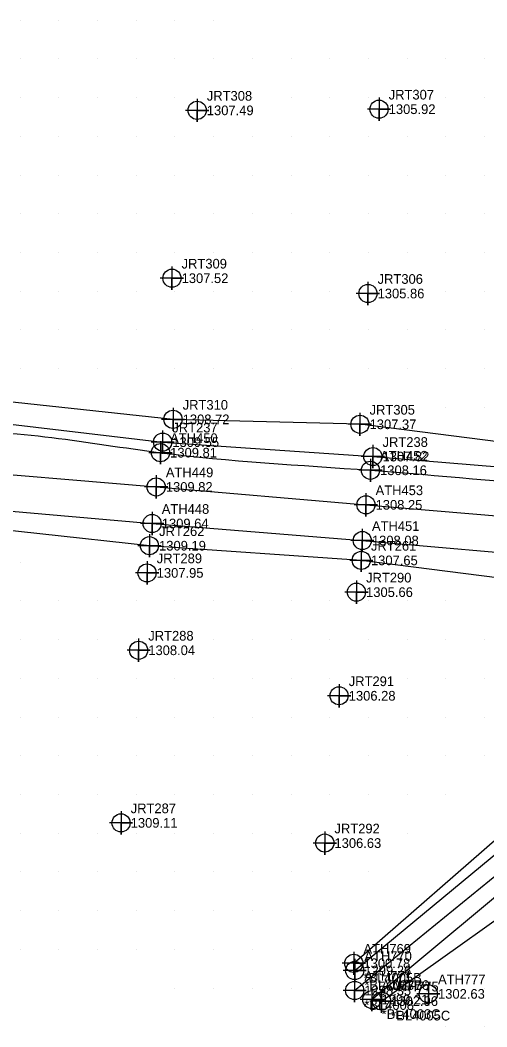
# Model space of a CAD drawing. Extents: x 1234484 to 1235382, y 695050 to 695510.
# Drawn here: x 1234680 to 1234800.6, y 695200 to 695460 of the extents above; entities that cross this region are included whole.
import ezdxf

# ---------------------------------------------------------------- set-up
doc = ezdxf.new("R2010")
doc.units = 0
for name, color, linetype in [('Exist DTM Breakline', 7, 'Continuous'), ('Exist DTM Breakline Cogo Comment', 7, 'Continuous'), ('Exist DTM Breakline Cogo Elevation', 7, 'Continuous'), ('Exist DTM Breakline Cogo Number', 7, 'Continuous'), ('Exist DTM Breakline Cogo Point CELL', 7, 'Continuous'), ('Exist DTM Breakline Underwater', 7, 'Continuous'), ('Exist DTM Crownline', 7, 'Continuous'), ('Exist DTM Crownline Cogo Elevation', 7, 'Continuous'), ('Exist DTM Crownline Cogo Number', 7, 'Continuous'), ('Exist DTM Crownline Cogo Point CELL', 7, 'Continuous'), ('Exist DTM Drainline Cogo Comment', 7, 'Continuous'), ('Exist DTM Drainline Cogo Elevation', 7, 'Continuous'), ('Exist DTM Drainline Cogo Number', 7, 'Continuous'), ('Exist DTM Drainline Cogo Point CELL', 7, 'Continuous'), ('Exist DTM QL2 LIDAR Elevation Point', 7, 'Continuous'), ('Exist DTM Regular Point CELL', 7, 'Continuous'), ('Exist DTM Regular Point Cogo Elevation', 7, 'Continuous'), ('Exist DTM Regular Point Cogo Number', 7, 'Continuous'), ('Exist DTM Regular Point Underwater CELL', 7, 'Continuous'), ('Exist DTM Regular Point Underwater Cogo Comment', 7, 'Continuous'), ('Exist DTM Regular Point Underwater Cogo Elevation', 7, 'Continuous'), ('Exist DTM Regular Point Underwater Cogo Number', 7, 'Continuous'), ('Exist Hydro Stream or Body of Water', 7, 'Continuous'), ('Exist Roads EOP', 7, 'Continuous'), ('Exist Roads EOP Cogo Elevation', 7, 'Continuous'), ('Exist Roads EOP Cogo Number', 7, 'Continuous'), ('Exist Roads EOP Cogo Point CELL', 7, 'Continuous')]:
    doc.layers.add(name, color=color, linetype=linetype)

msp = doc.modelspace()

# ---------------------------------------------------------------- linework, layer by layer
at = {"layer": 'Exist DTM Breakline'}
for points in [[(1234866.911, 695345.376), (1234823.763, 695348.478), (1234767.785, 695355.619), (1234719.498, 695356.897), (1234661.167, 695363.182), (1234623.376, 695365.3), (1234610.221, 695366.341), (1234608.231, 695369.759), (1234607.001, 695375.947)], [(1234608.156, 695366.132), (1234620.219, 695363.657), (1234657.83, 695357.954), (1234716.822, 695351.015), (1234771.134, 695347.284), (1234823.515, 695343.018), (1234867.598, 695341.251), (1234907.686, 695335.753), (1234932.171, 695332.602)], [(1234900.418, 695309.093), (1234843.128, 695314.065), (1234821.486, 695313.61), (1234768.142, 695320.476), (1234713.4, 695324.265), (1234656.708, 695330.451), (1234602.942, 695334.287)], [(1234766.2, 695216.412), (1234807.252, 695252.276), (1234839.673, 695274.467), (1234869.326, 695284.86), (1234890.801, 695299.09), (1234911.196, 695302.79), (1234918.594, 695307.818)], [(1234773.364, 695206.653), (1234820.257, 695240.015), (1234835.082, 695253.487), (1234852.804, 695270.766)]]:
    msp.add_lwpolyline(points, dxfattribs=at)
at = {"layer": 'Exist DTM Breakline Cogo Point CELL'}
for points in [[(1234719.498, 695359.897), (1234719.498, 695353.897), (1234719.498, 695356.897), (1234722.498, 695356.897), (1234716.498, 695356.897)], [(1234767.785, 695358.619), (1234767.785, 695352.619), (1234767.785, 695355.619), (1234770.785, 695355.619), (1234764.785, 695355.619)], [(1234716.822, 695354.015), (1234716.822, 695348.015), (1234716.822, 695351.015), (1234719.822, 695351.015), (1234713.822, 695351.015)], [(1234771.134, 695350.284), (1234771.134, 695344.284), (1234771.134, 695347.284), (1234774.134, 695347.284), (1234768.134, 695347.284)], [(1234713.4, 695327.265), (1234713.4, 695321.265), (1234713.4, 695324.265), (1234716.4, 695324.265), (1234710.4, 695324.265)], [(1234768.142, 695323.476), (1234768.142, 695317.476), (1234768.142, 695320.476), (1234771.142, 695320.476), (1234765.142, 695320.476)], [(1234766.2, 695219.412), (1234766.2, 695213.412), (1234766.2, 695216.412), (1234769.2, 695216.412), (1234763.2, 695216.412)], [(1234773.364, 695209.653), (1234773.364, 695203.653), (1234773.364, 695206.653), (1234776.364, 695206.653), (1234770.364, 695206.653)]]:
    msp.add_lwpolyline(points, dxfattribs=at)
for centre in [(1234719.498, 695356.897), (1234767.785, 695355.619), (1234716.822, 695351.015), (1234771.134, 695347.284), (1234713.4, 695324.265), (1234768.142, 695320.476), (1234766.2, 695216.412), (1234773.364, 695206.653)]:
    msp.add_circle(centre, 2.344, dxfattribs=at)
at = {"layer": 'Exist DTM Breakline Underwater'}
msp.add_lwpolyline([(1234766.421, 695209.389), (1234812.885, 695247.237), (1234843.411, 695272.621), (1234869.986, 695279.055), (1234895.378, 695289.036), (1234916.238, 695295.408), (1234934.131, 695306.081), (1234961.466, 695329.617), (1234991.436, 695342.664), (1235009.265, 695346.147), (1235040.352, 695365.623), (1235072.367, 695380.008), (1235092.174, 695396.335)], dxfattribs=at)
at = {"layer": 'Exist DTM Crownline'}
msp.add_lwpolyline([(1234511.603, 695359.057), (1234605.73, 695349.422), (1234657.657, 695344.297), (1234715.146, 695339.445), (1234769.335, 695334.825), (1234822.546, 695330.321), (1234845.176, 695328.304), (1234903.738, 695322.57)], dxfattribs=at)
at = {"layer": 'Exist DTM Crownline Cogo Point CELL'}
for points in [[(1234715.146, 695342.445), (1234715.146, 695336.445), (1234715.146, 695339.445), (1234718.146, 695339.445), (1234712.146, 695339.445)], [(1234769.335, 695337.825), (1234769.335, 695331.825), (1234769.335, 695334.825), (1234772.335, 695334.825), (1234766.335, 695334.825)]]:
    msp.add_lwpolyline(points, dxfattribs=at)
for centre in [(1234715.146, 695339.445), (1234769.335, 695334.825)]:
    msp.add_circle(centre, 2.344, dxfattribs=at)
at = {"layer": 'Exist DTM Drainline Cogo Point CELL'}
for points in [[(1234766.439, 695217.543), (1234766.439, 695211.543), (1234766.439, 695214.543), (1234769.439, 695214.543), (1234763.439, 695214.543)], [(1234770.872, 695210.044), (1234770.872, 695204.044), (1234770.872, 695207.044), (1234773.872, 695207.044), (1234767.872, 695207.044)]]:
    msp.add_lwpolyline(points, dxfattribs=at)
for centre in [(1234766.439, 695214.543), (1234770.872, 695207.044)]:
    msp.add_circle(centre, 2.344, dxfattribs=at)
at = {"layer": 'Exist DTM QL2 LIDAR Elevation Point'}
for p, q in [((1234680, 695460), (1234680, 695460)), ((1234690, 695460), (1234690, 695460)), ((1234700, 695460), (1234700, 695460)), ((1234710, 695460), (1234710, 695460)), ((1234720, 695460), (1234720, 695460)), ((1234730, 695460), (1234730, 695460)), ((1234680, 695450), (1234680, 695450)), ((1234690, 695450), (1234690, 695450)), ((1234700, 695450), (1234700, 695450)), ((1234710, 695450), (1234710, 695450)), ((1234720, 695450), (1234720, 695450)), ((1234730, 695450), (1234730, 695450)), ((1234740, 695450), (1234740, 695450)), ((1234750, 695450), (1234750, 695450)), ((1234760, 695450), (1234760, 695450)), ((1234770, 695450), (1234770, 695450)), ((1234780, 695450), (1234780, 695450)), ((1234790, 695450), (1234790, 695450)), ((1234800, 695450), (1234800, 695450)), ((1234680, 695440), (1234680, 695440)), ((1234690, 695440), (1234690, 695440)), ((1234700, 695440), (1234700, 695440)), ((1234710, 695440), (1234710, 695440)), ((1234720, 695440), (1234720, 695440)), ((1234730, 695440), (1234730, 695440)), ((1234740, 695440), (1234740, 695440)), ((1234750, 695440), (1234750, 695440)), ((1234760, 695440), (1234760, 695440)), ((1234770, 695440), (1234770, 695440)), ((1234780, 695440), (1234780, 695440)), ((1234790, 695440), (1234790, 695440)), ((1234800, 695440), (1234800, 695440)), ((1234680, 695430), (1234680, 695430)), ((1234690, 695430), (1234690, 695430)), ((1234700, 695430), (1234700, 695430)), ((1234710, 695430), (1234710, 695430)), ((1234720, 695430), (1234720, 695430)), ((1234730, 695430), (1234730, 695430)), ((1234740, 695430), (1234740, 695430)), ((1234750, 695430), (1234750, 695430)), ((1234760, 695430), (1234760, 695430)), ((1234770, 695430), (1234770, 695430)), ((1234780, 695430), (1234780, 695430)), ((1234790, 695430), (1234790, 695430)), ((1234800, 695430), (1234800, 695430)), ((1234680, 695420), (1234680, 695420)), ((1234690, 695420), (1234690, 695420)), ((1234700, 695420), (1234700, 695420)), ((1234710, 695420), (1234710, 695420)), ((1234720, 695420), (1234720, 695420)), ((1234730, 695420), (1234730, 695420)), ((1234740, 695420), (1234740, 695420)), ((1234750, 695420), (1234750, 695420)), ((1234760, 695420), (1234760, 695420)), ((1234770, 695420), (1234770, 695420)), ((1234780, 695420), (1234780, 695420)), ((1234790, 695420), (1234790, 695420)), ((1234800, 695420), (1234800, 695420)), ((1234680, 695410), (1234680, 695410)), ((1234690, 695410), (1234690, 695410)), ((1234700, 695410), (1234700, 695410)), ((1234710, 695410), (1234710, 695410)), ((1234720, 695410), (1234720, 695410)), ((1234730, 695410), (1234730, 695410)), ((1234740, 695410), (1234740, 695410)), ((1234750, 695410), (1234750, 695410)), ((1234760, 695410), (1234760, 695410)), ((1234770, 695410), (1234770, 695410)), ((1234780, 695410), (1234780, 695410)), ((1234790, 695410), (1234790, 695410)), ((1234800, 695410), (1234800, 695410)), ((1234680, 695400), (1234680, 695400)), ((1234690, 695400), (1234690, 695400)), ((1234700, 695400), (1234700, 695400)), ((1234710, 695400), (1234710, 695400)), ((1234720, 695400), (1234720, 695400)), ((1234730, 695400), (1234730, 695400)), ((1234740, 695400), (1234740, 695400)), ((1234750, 695400), (1234750, 695400)), ((1234760, 695400), (1234760, 695400)), ((1234770, 695400), (1234770, 695400)), ((1234780, 695400), (1234780, 695400)), ((1234790, 695400), (1234790, 695400)), ((1234800, 695400), (1234800, 695400)), ((1234680, 695390), (1234680, 695390)), ((1234690, 695390), (1234690, 695390)), ((1234700, 695390), (1234700, 695390)), ((1234710, 695390), (1234710, 695390)), ((1234720, 695390), (1234720, 695390)), ((1234730, 695390), (1234730, 695390)), ((1234740, 695390), (1234740, 695390)), ((1234750, 695390), (1234750, 695390)), ((1234760, 695390), (1234760, 695390)), ((1234770, 695390), (1234770, 695390)), ((1234780, 695390), (1234780, 695390)), ((1234790, 695390), (1234790, 695390)), ((1234800, 695390), (1234800, 695390)), ((1234680, 695380), (1234680, 695380)), ((1234690, 695380), (1234690, 695380)), ((1234700, 695380), (1234700, 695380)), ((1234710, 695380), (1234710, 695380)), ((1234720, 695380), (1234720, 695380)), ((1234730, 695380), (1234730, 695380)), ((1234740, 695380), (1234740, 695380)), ((1234750, 695380), (1234750, 695380)), ((1234760, 695380), (1234760, 695380)), ((1234770, 695380), (1234770, 695380)), ((1234780, 695380), (1234780, 695380)), ((1234790, 695380), (1234790, 695380)), ((1234800, 695380), (1234800, 695380)), ((1234680, 695370), (1234680, 695370)), ((1234690, 695370), (1234690, 695370)), ((1234700, 695370), (1234700, 695370)), ((1234710, 695370), (1234710, 695370)), ((1234720, 695370), (1234720, 695370)), ((1234730, 695370), (1234730, 695370)), ((1234740, 695370), (1234740, 695370)), ((1234750, 695370), (1234750, 695370)), ((1234760, 695370), (1234760, 695370)), ((1234770, 695370), (1234770, 695370)), ((1234780, 695370), (1234780, 695370)), ((1234790, 695370), (1234790, 695370)), ((1234800, 695370), (1234800, 695370)), ((1234780, 695360), (1234780, 695360)), ((1234790, 695360), (1234790, 695360)), ((1234800, 695360), (1234800, 695360)), ((1234680, 695320), (1234680, 695320)), ((1234680, 695310), (1234680, 695310)), ((1234690, 695310), (1234690, 695310)), ((1234700, 695310), (1234700, 695310)), ((1234710, 695310), (1234710, 695310)), ((1234720, 695310), (1234720, 695310)), ((1234730, 695310), (1234730, 695310)), ((1234740, 695310), (1234740, 695310)), ((1234750, 695310), (1234750, 695310)), ((1234760, 695310), (1234760, 695310)), ((1234770, 695310), (1234770, 695310)), ((1234780, 695310), (1234780, 695310)), ((1234790, 695310), (1234790, 695310)), ((1234680, 695300), (1234680, 695300)), ((1234690, 695300), (1234690, 695300)), ((1234700, 695300), (1234700, 695300)), ((1234710, 695300), (1234710, 695300)), ((1234720, 695300), (1234720, 695300)), ((1234730, 695300), (1234730, 695300)), ((1234740, 695300), (1234740, 695300)), ((1234750, 695300), (1234750, 695300)), ((1234760, 695300), (1234760, 695300)), ((1234770, 695300), (1234770, 695300)), ((1234780, 695300), (1234780, 695300)), ((1234790, 695300), (1234790, 695300)), ((1234800, 695300), (1234800, 695300)), ((1234680, 695290), (1234680, 695290)), ((1234690, 695290), (1234690, 695290)), ((1234700, 695290), (1234700, 695290)), ((1234710, 695290), (1234710, 695290)), ((1234720, 695290), (1234720, 695290)), ((1234730, 695290), (1234730, 695290)), ((1234740, 695290), (1234740, 695290)), ((1234750, 695290), (1234750, 695290)), ((1234760, 695290), (1234760, 695290)), ((1234770, 695290), (1234770, 695290)), ((1234780, 695290), (1234780, 695290)), ((1234790, 695290), (1234790, 695290)), ((1234800, 695290), (1234800, 695290)), ((1234680, 695280), (1234680, 695280)), ((1234690, 695280), (1234690, 695280)), ((1234700, 695280), (1234700, 695280)), ((1234710, 695280), (1234710, 695280)), ((1234720, 695280), (1234720, 695280)), ((1234730, 695280), (1234730, 695280)), ((1234740, 695280), (1234740, 695280)), ((1234750, 695280), (1234750, 695280)), ((1234760, 695280), (1234760, 695280)), ((1234770, 695280), (1234770, 695280)), ((1234780, 695280), (1234780, 695280)), ((1234790, 695280), (1234790, 695280)), ((1234800, 695280), (1234800, 695280)), ((1234680, 695270), (1234680, 695270)), ((1234690, 695270), (1234690, 695270)), ((1234700, 695270), (1234700, 695270)), ((1234710, 695270), (1234710, 695270)), ((1234720, 695270), (1234720, 695270)), ((1234730, 695270), (1234730, 695270)), ((1234740, 695270), (1234740, 695270)), ((1234750, 695270), (1234750, 695270)), ((1234760, 695270), (1234760, 695270)), ((1234770, 695270), (1234770, 695270)), ((1234780, 695270), (1234780, 695270)), ((1234790, 695270), (1234790, 695270)), ((1234800, 695270), (1234800, 695270)), ((1234680, 695260), (1234680, 695260)), ((1234690, 695260), (1234690, 695260)), ((1234700, 695260), (1234700, 695260)), ((1234710, 695260), (1234710, 695260)), ((1234720, 695260), (1234720, 695260)), ((1234730, 695260), (1234730, 695260)), ((1234740, 695260), (1234740, 695260)), ((1234750, 695260), (1234750, 695260)), ((1234760, 695260), (1234760, 695260)), ((1234770, 695260), (1234770, 695260)), ((1234780, 695260), (1234780, 695260)), ((1234790, 695260), (1234790, 695260)), ((1234680, 695250), (1234680, 695250)), ((1234690, 695250), (1234690, 695250)), ((1234700, 695250), (1234700, 695250)), ((1234710, 695250), (1234710, 695250)), ((1234720, 695250), (1234720, 695250)), ((1234730, 695250), (1234730, 695250)), ((1234740, 695250), (1234740, 695250)), ((1234750, 695250), (1234750, 695250)), ((1234760, 695250), (1234760, 695250)), ((1234770, 695250), (1234770, 695250)), ((1234780, 695250), (1234780, 695250)), ((1234680, 695240), (1234680, 695240)), ((1234690, 695240), (1234690, 695240)), ((1234700, 695240), (1234700, 695240)), ((1234710, 695240), (1234710, 695240)), ((1234720, 695240), (1234720, 695240)), ((1234730, 695240), (1234730, 695240)), ((1234740, 695240), (1234740, 695240)), ((1234750, 695240), (1234750, 695240)), ((1234760, 695240), (1234760, 695240)), ((1234770, 695240), (1234770, 695240)), ((1234680, 695230), (1234680, 695230)), ((1234690, 695230), (1234690, 695230)), ((1234700, 695230), (1234700, 695230)), ((1234710, 695230), (1234710, 695230)), ((1234720, 695230), (1234720, 695230)), ((1234730, 695230), (1234730, 695230)), ((1234740, 695230), (1234740, 695230)), ((1234750, 695230), (1234750, 695230)), ((1234760, 695230), (1234760, 695230)), ((1234680, 695220), (1234680, 695220)), ((1234690, 695220), (1234690, 695220)), ((1234700, 695220), (1234700, 695220)), ((1234710, 695220), (1234710, 695220)), ((1234720, 695220), (1234720, 695220)), ((1234730, 695220), (1234730, 695220)), ((1234740, 695220), (1234740, 695220)), ((1234750, 695220), (1234750, 695220)), ((1234720, 695210), (1234720, 695210)), ((1234730, 695210), (1234730, 695210)), ((1234740, 695210), (1234740, 695210)), ((1234750, 695210), (1234750, 695210)), ((1234760, 695210), (1234760, 695210)), ((1234800, 695210), (1234800, 695210)), ((1234790, 695200), (1234790, 695200)), ((1234800, 695200), (1234800, 695200))]:
    msp.add_line(p, q, dxfattribs=at)
at = {"layer": 'Exist DTM Regular Point CELL'}
for points in [[(1234725.732, 695439.701), (1234725.732, 695433.701), (1234725.732, 695436.701), (1234728.732, 695436.701), (1234722.732, 695436.701)], [(1234772.723, 695439.998), (1234772.723, 695433.998), (1234772.723, 695436.998), (1234775.723, 695436.998), (1234769.723, 695436.998)], [(1234719.217, 695396.346), (1234719.217, 695390.346), (1234719.217, 695393.346), (1234722.217, 695393.346), (1234716.217, 695393.346)], [(1234769.856, 695392.397), (1234769.856, 695386.397), (1234769.856, 695389.397), (1234772.856, 695389.397), (1234766.856, 695389.397)], [(1234712.79, 695320.242), (1234712.79, 695314.242), (1234712.79, 695317.242), (1234715.79, 695317.242), (1234709.79, 695317.242)], [(1234766.879, 695315.27), (1234766.879, 695309.27), (1234766.879, 695312.27), (1234769.879, 695312.27), (1234763.879, 695312.27)], [(1234710.611, 695300.261), (1234710.611, 695294.261), (1234710.611, 695297.261), (1234713.611, 695297.261), (1234707.611, 695297.261)], [(1234762.4, 695288.509), (1234762.4, 695282.509), (1234762.4, 695285.509), (1234765.4, 695285.509), (1234759.4, 695285.509)], [(1234706.067, 695255.685), (1234706.067, 695249.685), (1234706.067, 695252.685), (1234709.067, 695252.685), (1234703.067, 695252.685)], [(1234758.711, 695250.468), (1234758.711, 695244.468), (1234758.711, 695247.468), (1234761.711, 695247.468), (1234755.711, 695247.468)], [(1234785.464, 695211.52), (1234785.464, 695205.52), (1234785.464, 695208.52), (1234788.464, 695208.52), (1234782.464, 695208.52)]]:
    msp.add_lwpolyline(points, dxfattribs=at)
for centre in [(1234725.732, 695436.701), (1234772.723, 695436.998), (1234719.217, 695393.346), (1234769.856, 695389.397), (1234712.79, 695317.242), (1234766.879, 695312.27), (1234710.611, 695297.261), (1234762.4, 695285.509), (1234706.067, 695252.685), (1234758.711, 695247.468), (1234785.464, 695208.52)]:
    msp.add_circle(centre, 2.344, dxfattribs=at)
at = {"layer": 'Exist DTM Regular Point Underwater CELL'}
msp.add_lwpolyline([(1234766.421, 695212.389), (1234766.421, 695206.389), (1234766.421, 695209.389), (1234769.421, 695209.389), (1234763.421, 695209.389)], dxfattribs=at)
msp.add_circle((1234766.421, 695209.389), 2.344, dxfattribs=at)
at = {"layer": 'Exist Hydro Stream or Body of Water'}
for points in [[(1234766.439, 695214.543), (1234809.451, 695250.146), (1234840.783, 695273.683), (1234870.231, 695281.467), (1234894.384, 695292.767), (1234915.014, 695298.345), (1234929.933, 695306.511), (1234953.845, 695329.807), (1234986.204, 695341.472), (1235008.526, 695348.915), (1235037.336, 695368.653), (1235069.491, 695383.302), (1235088.448, 695400.861)], [(1234770.872, 695207.044), (1234815.763, 695244.4), (1234847.025, 695270.849), (1234870.723, 695276.867), (1234895.944, 695286.356), (1234916.555, 695293.487), (1234933.154, 695302.663)]]:
    msp.add_lwpolyline(points, dxfattribs=at)
at = {"layer": 'Exist Roads EOP'}
msp.add_lwpolyline([(1234510.022, 695349.783), (1234546.237, 695345.927), (1234604.07, 695340.356), (1234657.035, 695335.026), (1234714.094, 695329.996), (1234768.395, 695325.598), (1234821.671, 695320.933), (1234844.56, 695319.029)], dxfattribs=at)
msp.add_spline([(1234605.599, 695398.165), (1234601.696, 695381.855), (1234613.593, 695357.692), (1234658.916, 695353.52), (1234716.264, 695348.291), (1234770.499, 695343.743), (1234823.09, 695339.258), (1234845.762, 695337.371), (1234903.754, 695331.785), (1234928.613, 695329.389)], degree=3, dxfattribs=at)
at = {"layer": 'Exist Roads EOP Cogo Point CELL'}
for points in [[(1234716.264, 695351.291), (1234716.264, 695345.291), (1234716.264, 695348.291), (1234719.264, 695348.291), (1234713.264, 695348.291)], [(1234770.499, 695346.743), (1234770.499, 695340.743), (1234770.499, 695343.743), (1234773.499, 695343.743), (1234767.499, 695343.743)], [(1234714.094, 695332.996), (1234714.094, 695326.996), (1234714.094, 695329.996), (1234717.094, 695329.996), (1234711.094, 695329.996)], [(1234768.395, 695328.598), (1234768.395, 695322.598), (1234768.395, 695325.598), (1234771.395, 695325.598), (1234765.395, 695325.598)]]:
    msp.add_lwpolyline(points, dxfattribs=at)
for centre in [(1234716.264, 695348.291), (1234770.499, 695343.743), (1234714.094, 695329.996), (1234768.395, 695325.598)]:
    msp.add_circle(centre, 2.344, dxfattribs=at)

# ---------------------------------------------------------------- texts
at = {"layer": 'Exist DTM Breakline Cogo Comment'}
for s, p in [('*BL4005B', (1234768.7, 695211.412)), ('*BL4005C', (1234775.864, 695201.653))]:
    msp.add_text(s, height=2.5, dxfattribs=at).set_placement(p)
at = {"layer": 'Exist DTM Breakline Cogo Elevation'}
for s, p in [('1308.72', (1234721.998, 695355.647)), ('1307.37', (1234770.285, 695354.369)), ('1309.55', (1234719.322, 695349.765)), ('1307.82', (1234773.634, 695346.034)), ('1309.19', (1234715.9, 695323.015)), ('1307.65', (1234770.642, 695319.226)), ('1300.78', (1234768.7, 695215.162)), ('1302.96', (1234775.864, 695205.403))]:
    msp.add_text(s, height=2.5, dxfattribs=at).set_placement(p)
at = {"layer": 'Exist DTM Breakline Cogo Number'}
for s, p in [('JRT310', (1234721.998, 695359.397)), ('JRT305', (1234770.285, 695358.119)), ('JRT237', (1234719.322, 695353.515)), ('JRT238', (1234773.634, 695349.784)), ('JRT262', (1234715.9, 695326.765)), ('JRT261', (1234770.642, 695322.976)), ('ATH769', (1234768.7, 695218.912)), ('ATH775', (1234775.864, 695209.153))]:
    msp.add_text(s, height=2.5, dxfattribs=at).set_placement(p)
at = {"layer": 'Exist DTM Crownline Cogo Elevation'}
for s, p in [('1309.82', (1234717.646, 695338.195)), ('1308.25', (1234771.835, 695333.575))]:
    msp.add_text(s, height=2.5, dxfattribs=at).set_placement(p)
at = {"layer": 'Exist DTM Crownline Cogo Number'}
for s, p in [('ATH449', (1234717.646, 695341.945)), ('ATH453', (1234771.835, 695337.325))]:
    msp.add_text(s, height=2.5, dxfattribs=at).set_placement(p)
at = {"layer": 'Exist DTM Drainline Cogo Comment'}
for s, p in [('*BL4003B', (1234768.939, 695209.543)), ('*BL4003C', (1234773.372, 695202.044))]:
    msp.add_text(s, height=2.5, dxfattribs=at).set_placement(p)
at = {"layer": 'Exist DTM Drainline Cogo Elevation'}
for s, p in [('1299.26', (1234768.939, 695213.293)), ('1299.21', (1234773.372, 695205.794))]:
    msp.add_text(s, height=2.5, dxfattribs=at).set_placement(p)
at = {"layer": 'Exist DTM Drainline Cogo Number'}
for s, p in [('ATH770', (1234768.939, 695217.043)), ('ATH776', (1234773.372, 695209.544))]:
    msp.add_text(s, height=2.5, dxfattribs=at).set_placement(p)
at = {"layer": 'Exist DTM Regular Point Cogo Elevation'}
for s, p in [('1307.49', (1234728.232, 695435.451)), ('1305.92', (1234775.223, 695435.748)), ('1307.52', (1234721.717, 695392.096)), ('1305.86', (1234772.356, 695388.147)), ('1307.95', (1234715.29, 695315.992)), ('1305.66', (1234769.379, 695311.02)), ('1308.04', (1234713.111, 695296.011)), ('1306.28', (1234764.9, 695284.259)), ('1309.11', (1234708.567, 695251.435)), ('1306.63', (1234761.211, 695246.218)), ('1302.63', (1234787.964, 695207.27))]:
    msp.add_text(s, height=2.5, dxfattribs=at).set_placement(p)
at = {"layer": 'Exist DTM Regular Point Cogo Number'}
for s, p in [('JRT308', (1234728.232, 695439.201)), ('JRT307', (1234775.223, 695439.498)), ('JRT309', (1234721.717, 695395.846)), ('JRT306', (1234772.356, 695391.897)), ('JRT289', (1234715.29, 695319.742)), ('JRT290', (1234769.379, 695314.77)), ('JRT288', (1234713.111, 695299.761)), ('JRT291', (1234764.9, 695288.009)), ('JRT287', (1234708.567, 695255.185)), ('JRT292', (1234761.211, 695249.968)), ('ATH777', (1234787.964, 695211.02))]:
    msp.add_text(s, height=2.5, dxfattribs=at).set_placement(p)
at = {"layer": 'Exist DTM Regular Point Underwater Cogo Comment'}
msp.add_text('*BL4008', height=2.5, dxfattribs=at).set_placement((1234768.921, 695204.389))
at = {"layer": 'Exist DTM Regular Point Underwater Cogo Elevation'}
msp.add_text('1298.35', height=2.5, dxfattribs=at).set_placement((1234768.921, 695208.139))
at = {"layer": 'Exist DTM Regular Point Underwater Cogo Number'}
msp.add_text('ATH771', height=2.5, dxfattribs=at).set_placement((1234768.921, 695211.889))
at = {"layer": 'Exist Roads EOP Cogo Elevation'}
for s, p in [('1309.81', (1234718.764, 695347.041)), ('1308.16', (1234772.999, 695342.493)), ('1309.64', (1234716.594, 695328.746)), ('1308.08', (1234770.895, 695324.348))]:
    msp.add_text(s, height=2.5, dxfattribs=at).set_placement(p)
at = {"layer": 'Exist Roads EOP Cogo Number'}
for s, p in [('ATH450', (1234718.764, 695350.791)), ('ATH452', (1234772.999, 695346.243)), ('ATH448', (1234716.594, 695332.496)), ('ATH451', (1234770.895, 695328.098))]:
    msp.add_text(s, height=2.5, dxfattribs=at).set_placement(p)

doc.saveas('drawing.dxf')
